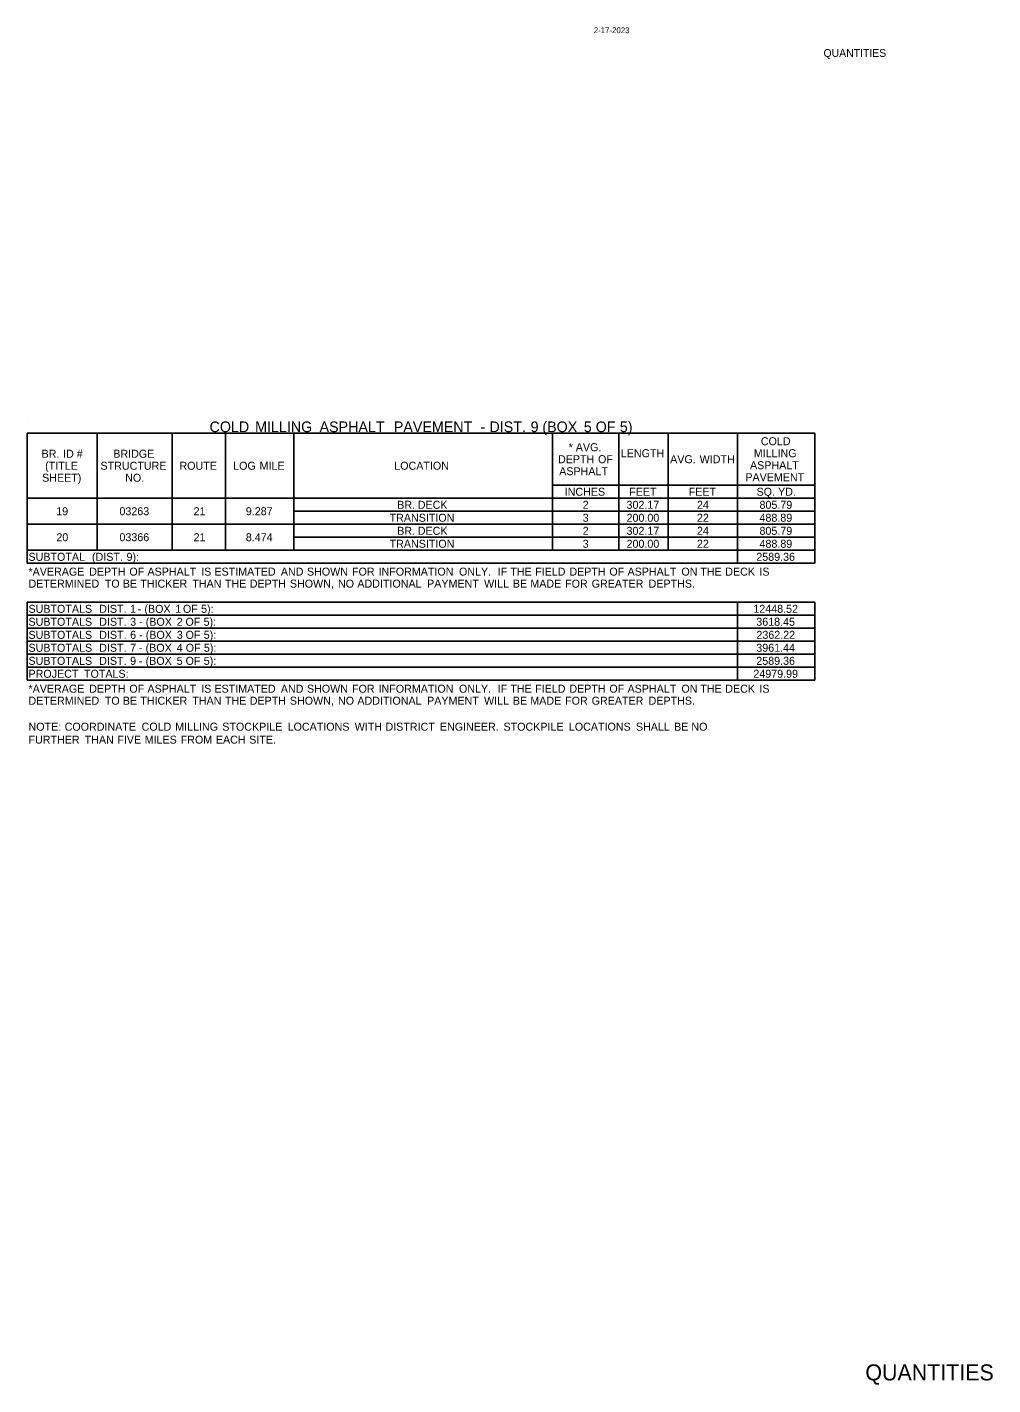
# Model space of a CAD drawing. Extents: x 544255 to 1930787, y -1947044 to 596640.
# Drawn here: x 554569 to 555293, y -1947044 to -1946026 of the extents above; entities that cross this region are included whole.
import ezdxf

# ---------------------------------------------------------------- set-up
doc = ezdxf.new("R2010")
doc.units = 0
for name, color, linetype in [('Default', 7, 'Continuous'), ('R_Border', 7, 'Continuous'), ('R_Border Prem', 7, 'Continuous')]:
    doc.layers.add(name, color=color, linetype=linetype)

msp = doc.modelspace()

# ---------------------------------------------------------------- linework, layer by layer
at = {"layer": 'Default'}
for p, q in [((554569, -1946320.9), (554569, -1946320.9)), ((554569, -1946330.6), (555159.8, -1946330.6)), ((554569, -1946330.6), (555159.8, -1946330.6)), ((554569, -1946428.1), (554569, -1946330.6)), ((554621.6, -1946418.4), (554621.6, -1946330.6)), ((554677.7, -1946418.4), (554677.7, -1946330.6)), ((554717.7, -1946418.4), (554717.7, -1946330.6)), ((554768.9, -1946418.4), (554768.9, -1946330.6)), ((554962.9, -1946418.4), (554962.9, -1946330.6)), ((555012.6, -1946418.4), (555012.6, -1946330.6)), ((555049.7, -1946418.4), (555049.7, -1946330.6)), ((555101.8, -1946428.1), (555101.8, -1946330.6)), ((555159.8, -1946428.1), (555159.8, -1946330.6)), ((554569, -1946379.4), (555159.8, -1946379.4)), ((554962.9, -1946369.6), (555049.7, -1946369.6)), ((554962.9, -1946369.6), (555012.6, -1946369.6)), ((555012.6, -1946369.6), (555159.8, -1946369.6)), ((555049.7, -1946379.4), (555049.7, -1946369.6)), ((554768.9, -1946389.1), (555159.8, -1946389.1)), ((554569, -1946398.9), (554768.9, -1946398.9)), ((554569, -1946398.9), (555159.8, -1946398.9)), ((554768.9, -1946398.9), (555159.8, -1946398.9)), ((554768.9, -1946408.6), (555159.8, -1946408.6)), ((554569, -1946418.4), (554768.9, -1946418.4)), ((554569, -1946418.4), (555159.8, -1946418.4)), ((554768.9, -1946418.4), (555159.8, -1946418.4)), ((554569, -1946428.1), (555159.8, -1946428.1)), ((554569, -1946457.4), (555159.8, -1946457.4)), ((554569, -1946457.4), (555159.8, -1946457.4)), ((554569, -1946515.9), (554569, -1946457.4)), ((555101.8, -1946515.9), (555101.8, -1946457.4)), ((555159.8, -1946515.9), (555159.8, -1946457.4)), ((554569, -1946467.1), (555159.8, -1946467.1)), ((554569, -1946476.9), (555159.8, -1946476.9)), ((554569, -1946486.6), (555159.8, -1946486.6)), ((554569, -1946496.4), (555159.8, -1946496.4)), ((554569, -1946506.1), (555159.8, -1946506.1)), ((554569, -1946515.9), (555159.8, -1946515.9))]:
    msp.add_line(p, q, dxfattribs=at)

# ---------------------------------------------------------------- texts
for s, height, p in [('COLD', 8, (554705.8, -1946329.8)), (' MILLING', 8, (554737, -1946329.8)), (' ASPHALT', 8, (554785.3, -1946329.8)), (' PAVEMENT', 8, (554841, -1946329.8)), (' -', 8, (554906, -1946329.8)), (' DIST.', 8, (554912.7, -1946329.8)), (' 9', 8, (554943.6, -1946329.8)), (' (BOX', 8, (554952.4, -1946329.8)), (' 5', 8, (554983.5, -1946329.8)), (' OF', 8, (554992.4, -1946329.8)), (' 5)', 8, (555010.5, -1946329.8)), ('*', 6, (554975.1, -1946344.1)), (' AVG.', 6, (554978.2, -1946344.1)), ('COLD', 6, (555119.2, -1946339.6)), ('BR.', 6, (554579.8, -1946349)), (' ID', 6, (554593.7, -1946349)), (' #', 6, (554604, -1946349)), ('BRIDGE', 6, (554633.6, -1946349)), ('DEPTH', 6, (554967.1, -1946353.1)), (' OF', 6, (554994.9, -1946353.1)), ('LENGTH', 6, (555014.2, -1946348.6)), ('AVG.', 6, (555051.2, -1946353.1)), (' WIDTH', 6, (555071.1, -1946353.1)), ('MILLING', 6, (555113.9, -1946348.6)), ('(TITLE', 6, (554582.5, -1946358)), ('STRUCTURE', 6, (554624, -1946358)), ('ROUTE', 6, (554683.2, -1946358)), ('LOG', 6, (554723.5, -1946358)), (' MILE', 6, (554741.1, -1946358)), ('LOCATION', 6, (554844.3, -1946358)), ('ASPHALT', 6, (554968, -1946362.1)), ('ASPHALT', 6, (555111.1, -1946357.6)), ('SHEET)', 6, (554580.2, -1946367)), ('NO.', 6, (554642.5, -1946367)), ('PAVEMENT', 6, (555107.6, -1946366.6)), ('INCHES', 6, (554972.1, -1946377.5)), ('FEET', 6, (555020.5, -1946377.5)), ('FEET', 6, (555065.1, -1946377.5)), ('SQ.', 6, (555116, -1946377.5)), (' YD.', 6, (555129.9, -1946377.5)), ('19', 6, (554590.8, -1946392.1)), ('03263', 6, (554638.2, -1946392.1)), ('21', 6, (554693.8, -1946392.1)), ('9.287', 6, (554733, -1946392.1)), ('BR.', 6, (554846.5, -1946387.3)), (' DECK', 6, (554859.7, -1946387.3)), ('2', 6, (554985.6, -1946387.3)), ('302.17', 6, (555018.5, -1946387.3)), ('24', 6, (555071.3, -1946387.3)), ('805.79', 6, (555118.2, -1946387.3)), ('TRANSITION', 6, (554840.8, -1946397)), ('3', 6, (554985.6, -1946397)), ('200.00', 6, (555018.5, -1946397)), ('22', 6, (555071.3, -1946397)), ('488.89', 6, (555118.2, -1946397)), ('20', 6, (554590.9, -1946411.6)), ('03366', 6, (554638.2, -1946411.6)), ('21', 6, (554693.8, -1946411.6)), ('8.474', 6, (554733, -1946411.6)), ('BR.', 6, (554846.5, -1946406.8)), (' DECK', 6, (554859.7, -1946406.8)), ('2', 6, (554985.6, -1946406.8)), ('302.17', 6, (555018.5, -1946406.8)), ('24', 6, (555071.3, -1946406.8)), ('805.79', 6, (555118.2, -1946406.8)), ('SUBTOTAL', 6, (554570, -1946426.3)), (' (DIST.', 6, (554615.4, -1946426.3)), (' 9):', 6, (554641.3, -1946426.3)), ('TRANSITION', 6, (554840.8, -1946416.5)), ('3', 6, (554985.6, -1946416.5)), ('200.00', 6, (555018.5, -1946416.5)), ('22', 6, (555071.3, -1946416.5)), ('2589.36', 6, (555115.8, -1946426.3)), ('488.89', 6, (555118.2, -1946416.5)), ('*AVERAGE', 6, (554570, -1946437.4)), ('DETERMINED', 6, (554570, -1946446.4)), (' DEPTH', 6, (554613.3, -1946437.4)), (' TO', 6, (554625, -1946446.4)), (' BE', 6, (554638.5, -1946446.4)), (' OF', 6, (554643.4, -1946437.4)), (' THICKER', 6, (554651.6, -1946446.4)), (' ASPHALT', 6, (554657, -1946437.4)), (' THAN', 6, (554690.6, -1946446.4)), (' IS', 6, (554697.3, -1946437.4)), (' ESTIMATED', 6, (554707.2, -1946437.4)), (' THE', 6, (554715.1, -1946446.4)), (' DEPTH', 6, (554733.7, -1946446.4)), (' AND', 6, (554757, -1946437.4)), (' SHOWN,', 6, (554763.8, -1946446.4)), (' SHOWN', 6, (554776.6, -1946437.4)), (' NO', 6, (554799.9, -1946446.4)), (' FOR', 6, (554810.4, -1946437.4)), (' ADDITIONAL', 6, (554814.4, -1946446.4)), (' INFORMATION', 6, (554830.3, -1946437.4)), (' PAYMENT', 6, (554866.7, -1946446.4)), (' ONLY.', 6, (554890.6, -1946437.4)), (' WILL', 6, (554909.4, -1946446.4)), ('  IF', 6, (554917.4, -1946437.4)), (' THE', 6, (554929.1, -1946437.4)), (' BE', 6, (554931, -1946446.4)), (' MADE', 6, (554944.1, -1946446.4)), (' FIELD', 6, (554947.7, -1946437.4)), (' FOR', 6, (554970.2, -1946446.4)), (' DEPTH', 6, (554973.4, -1946437.4)), (' GREATER', 6, (554990.1, -1946446.4)), (' OF', 6, (555003.4, -1946437.4)), (' ASPHALT', 6, (555017, -1946437.4)), (' DEPTHS.', 6, (555032.8, -1946446.4)), (' ON', 6, (555057.4, -1946437.4)), (' THE', 6, (555071.6, -1946437.4)), (' DECK', 6, (555090.3, -1946437.4)), (' IS', 6, (555115.9, -1946437.4)), ('SUBTOTALS', 6, (554570, -1946465.3)), (' DIST.', 6, (554620.8, -1946465.3)), (' 1', 6, (554644, -1946465.3)), (' (BOX', 6, (554654.7, -1946465.3)), (' 1', 6, (554677.9, -1946465.3)), (' OF', 6, (554683.6, -1946465.3)), (' 5):', 6, (554697.2, -1946465.3)), ('12448.52', 6, (555113.6, -1946465.3)), ('SUBTOTALS', 6, (554570, -1946475)), (' DIST.', 6, (554620.8, -1946475)), (' 3', 6, (554644, -1946475)), (' -', 6, (554649.6, -1946465.3)), (' (BOX', 6, (554655.7, -1946475)), (' 2', 6, (554678.9, -1946475)), (' OF', 6, (554685.5, -1946475)), (' 5):', 6, (554699.1, -1946475)), ('3618.45', 6, (555115.8, -1946475)), ('SUBTOTALS', 6, (554570, -1946484.8)), (' DIST.', 6, (554620.8, -1946484.8)), (' 6', 6, (554644, -1946484.8)), (' -', 6, (554650.6, -1946475)), (' (BOX', 6, (554655.7, -1946484.8)), (' 3', 6, (554679, -1946484.8)), (' OF', 6, (554685.6, -1946484.8)), (' 5):', 6, (554699.2, -1946484.8)), ('2362.22', 6, (555115.9, -1946484.8)), ('SUBTOTALS', 6, (554570, -1946494.5)), (' DIST.', 6, (554620.8, -1946494.5)), (' 7', 6, (554644, -1946494.5)), (' -', 6, (554650.7, -1946484.8)), (' (BOX', 6, (554655.6, -1946494.5)), (' 4', 6, (554678.9, -1946494.5)), (' OF', 6, (554685.7, -1946494.5)), (' 5):', 6, (554699.3, -1946494.5)), ('3961.44', 6, (555115.8, -1946494.5)), ('SUBTOTALS', 6, (554570, -1946504.3)), (' DIST.', 6, (554620.8, -1946504.3)), (' 9', 6, (554644, -1946504.3)), (' -', 6, (554650.6, -1946494.5)), (' -', 6, (554650.6, -1946504.3)), (' (BOX', 6, (554655.6, -1946504.3)), (' 5', 6, (554678.9, -1946504.3)), (' OF', 6, (554685.6, -1946504.3)), (' 5):', 6, (554699.2, -1946504.3)), ('2589.36', 6, (555115.8, -1946504.3)), ('PROJECT', 6, (554570, -1946514)), (' TOTALS:', 6, (554609.4, -1946514)), ('24979.99', 6, (555113.6, -1946514)), ('*AVERAGE', 6, (554570, -1946525.2)), (' DEPTH', 6, (554613.3, -1946525.2)), (' OF', 6, (554643.4, -1946525.2)), (' ASPHALT', 6, (554657, -1946525.2)), (' IS', 6, (554697.3, -1946525.2)), (' ESTIMATED', 6, (554707.2, -1946525.2)), (' AND', 6, (554757, -1946525.2)), (' SHOWN', 6, (554776.6, -1946525.2)), (' FOR', 6, (554810.4, -1946525.2)), (' INFORMATION', 6, (554830.3, -1946525.2)), (' ONLY.', 6, (554890.6, -1946525.2)), ('  IF', 6, (554917.4, -1946525.2)), (' THE', 6, (554929.1, -1946525.2)), (' FIELD', 6, (554947.7, -1946525.2)), (' DEPTH', 6, (554973.4, -1946525.2)), (' OF', 6, (555003.4, -1946525.2)), (' ASPHALT', 6, (555017, -1946525.2)), (' ON', 6, (555057.4, -1946525.2)), (' THE', 6, (555071.6, -1946525.2)), (' DECK', 6, (555090.3, -1946525.2)), (' IS', 6, (555115.9, -1946525.2)), ('DETERMINED', 6, (554570, -1946534.2)), (' TO', 6, (554625, -1946534.2)), (' BE', 6, (554638.5, -1946534.2)), (' THICKER', 6, (554651.6, -1946534.2)), (' THAN', 6, (554690.6, -1946534.2)), (' THE', 6, (554715.1, -1946534.2)), (' DEPTH', 6, (554733.7, -1946534.2)), (' SHOWN,', 6, (554763.8, -1946534.2)), (' NO', 6, (554799.9, -1946534.2)), (' ADDITIONAL', 6, (554814.4, -1946534.2)), (' PAYMENT', 6, (554866.7, -1946534.2)), (' WILL', 6, (554909.4, -1946534.2)), (' BE', 6, (554931, -1946534.2)), (' MADE', 6, (554944.1, -1946534.2)), (' FOR', 6, (554970.2, -1946534.2)), (' GREATER', 6, (554990.1, -1946534.2)), (' DEPTHS.', 6, (555032.8, -1946534.2)), ('NOTE:', 6, (554570, -1946553.7)), (' COORDINATE', 6, (554594.9, -1946553.7)), (' COLD', 6, (554652.6, -1946553.7)), (' MILLING', 6, (554677.8, -1946553.7)), (' STOCKPILE', 6, (554713.1, -1946553.7)), (' LOCATIONS', 6, (554762.1, -1946553.7)), (' WITH', 6, (554812.4, -1946553.7)), (' DISTRICT', 6, (554835.5, -1946553.7)), (' ENGINEER.', 6, (554876.3, -1946553.7)), (' STOCKPILE', 6, (554924, -1946553.7)), (' LOCATIONS', 6, (554973, -1946553.7)), (' SHALL', 6, (555023.3, -1946553.7)), (' BE', 6, (555051.9, -1946553.7)), (' NO', 6, (555064.9, -1946553.7)), ('FURTHER', 6, (554570, -1946563.4)), (' THAN', 6, (554609.9, -1946563.4)), (' FIVE', 6, (554634.4, -1946563.4)), (' MILES', 6, (554654.9, -1946563.4)), (' FROM', 6, (554681.9, -1946563.4)), (' EACH', 6, (554708.3, -1946563.4)), (' SITE.', 6, (554733.3, -1946563.4))]:
    msp.add_text(s, height=height, dxfattribs=at).set_placement(p)
at = {"layer": 'R_Border'}
msp.add_text('QUANTITIES', height=12, rotation=360, dxfattribs=at).set_placement((555197.6, -1947040.9))
at = {"layer": 'R_Border Prem'}
msp.add_text('2-17-2023', height=4.4, dxfattribs=at).set_placement((554993.9, -1946030.6))
msp.add_text('QUANTITIES', height=5.86, rotation=360, dxfattribs=at).set_placement((555166.2, -1946048.4))

doc.saveas('drawing.dxf')
